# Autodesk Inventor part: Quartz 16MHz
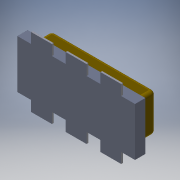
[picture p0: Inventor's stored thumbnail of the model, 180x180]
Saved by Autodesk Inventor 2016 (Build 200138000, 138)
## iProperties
Created: 2018-03
Part Number: Quartz 16MHz
Material: Générique
Document SubType Name: Modeling
Designer: Bruno
Density: 1 g/cm^3
Appearance: Par défaut
Author: Bruno
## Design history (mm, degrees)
feature "Composite1"
body "Srf1"
